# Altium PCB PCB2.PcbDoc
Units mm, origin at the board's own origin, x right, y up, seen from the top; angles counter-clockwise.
Board outline 184 x 101.95 mm, 2 copper layers (Top Layer, Bottom Layer); 27 components, 17 nets, 70 pads, 0 vias.
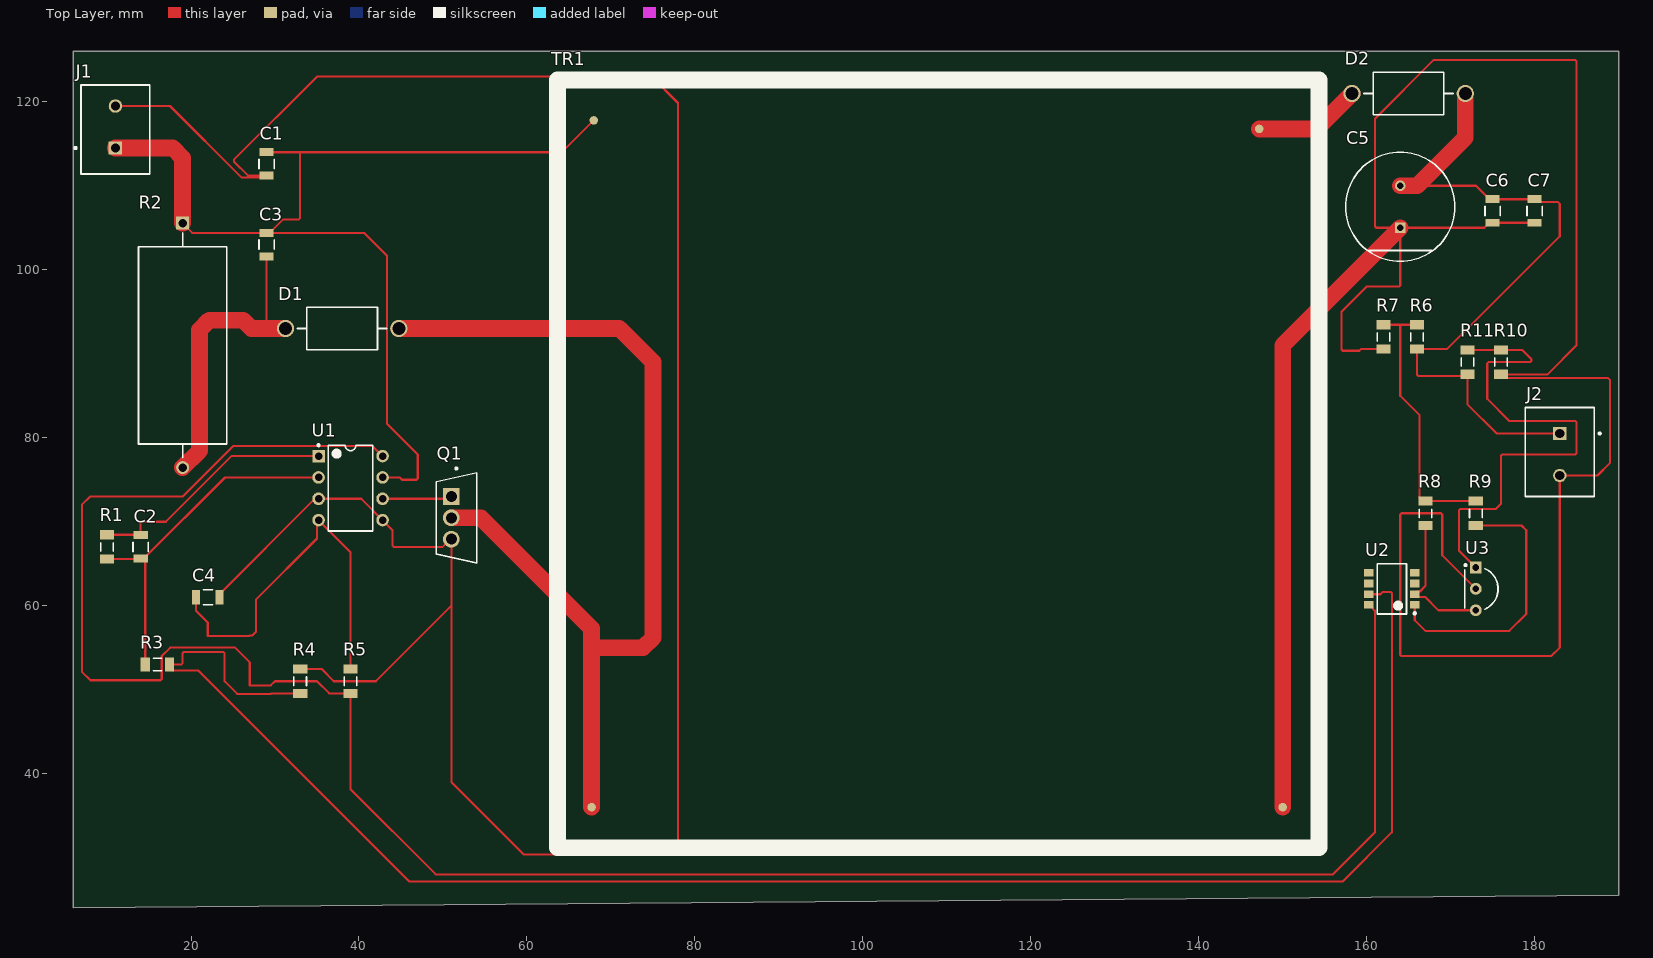
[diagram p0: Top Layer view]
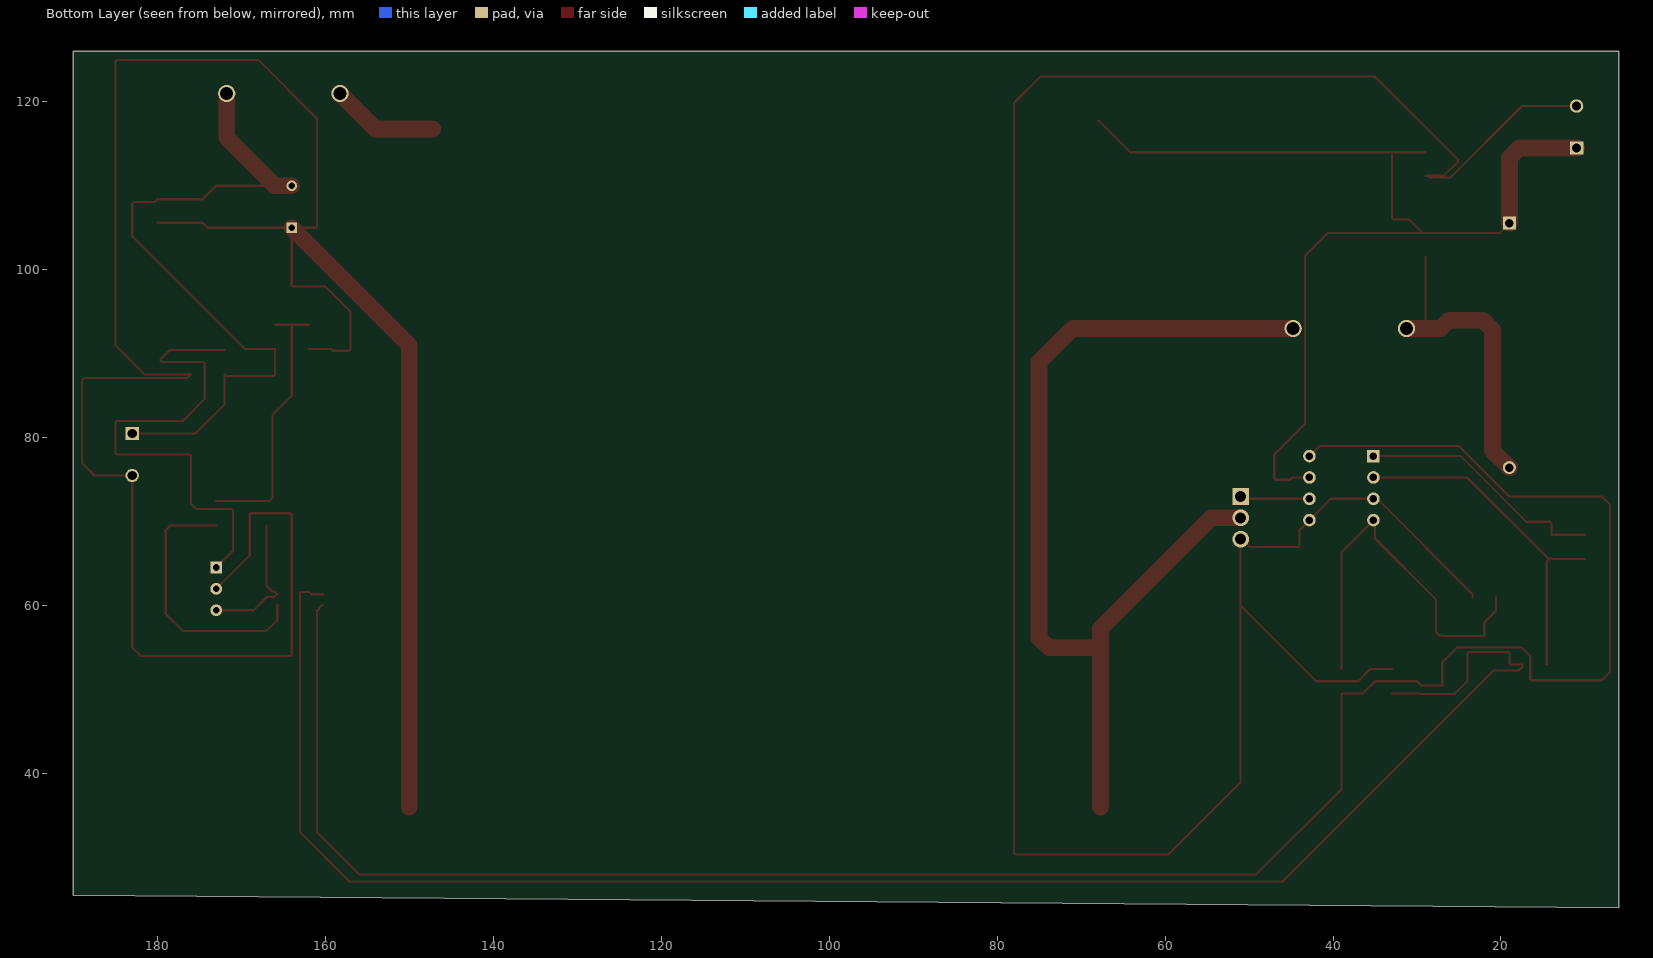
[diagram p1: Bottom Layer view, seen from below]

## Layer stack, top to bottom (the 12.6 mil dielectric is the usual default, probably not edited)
Top Solder: solder mask 0.0102, Solder Resist, Dk 3.5
Top Layer: signal copper 0.0356
Dielectric 1: dielectric 0.32, FR-4, Dk 4.8
Bottom Layer: signal copper 0.0356
Bottom Solder: solder mask 0.0102, Solder Resist, Dk 3.5

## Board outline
6,24.047 190,25.496 190,126 6,126
cut-out: 178.75,11.25

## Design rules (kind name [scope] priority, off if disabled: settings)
Clearance [All] p1: gap=0.254 ignorepadtopadclearanceinfootprint=FALSE except(0: Arc-Hole Track-Hole SMDPad-Hole THPad-Hole Via-Hole Fill-Hole Poly-Hole Region-Hole Text-Hole)
PolygonConnect [All] p1: connectstyle=Relief reliefconductorwidth=0.254 reliefentries=4 polygonreliefangle="90 Angle" airgapwidth=0.254
RoutingVias [All] p1: holewidth=0.711 width=1.27 viastyle="Through Hole" minholewidth=0.711 minwidth=1.27 maxholewidth=0.711 maxwidth=1.27
SolderMaskExpansion [All] p1: expansion=0.102 istentingtop=FALSE
Width [All] p1: maxlimit=22.254 minlimit=0.254 preferedwidth=0.254 minimp=50.000000 maximp=50.000000 favimp=50.000000
30 further rules are at their usual default settings.

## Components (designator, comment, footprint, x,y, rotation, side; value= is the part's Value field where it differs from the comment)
C1 "4.7uF (1206)" FP-C1206C-EB-MFG 29,112.6 r270 top value="1,000 pF"
C2 "1nF (1206)" FP-C1206C-EB-MFG 14,67 r90 top value="1,000 pF"
C3 "4.7uF (1206)" FP-C1206C-EB-MFG 29,103 r270 top value="1,000 pF"
C4 "1nF (1206)" FP-C1206C-EB-MFG 22,61 r0 top value="1,000 pF"
C5 "CAP 100uF UBX2A101MHL" FP-UBX2A101MHL-MFG 164,107.5 r90 top value=100uF
C6 "20uF (1206)" FP-C1206C-EB-MFG 175,107 r90 top value="1,000 pF"
C7 "1nF (1206)" FP-C1206C-EB-MFG 180,107 r90 top value="1,000 pF"
D1 "Schottky (MBR3100RLG)" ONSC-AXIAL_LEAD-2-267-05_V 38,93 r0 top
D2 "MUR460" ONSC-AXIAL_LEAD-2-267-05_V 165,121 r180 top
J1 "282836-2" TECO-282836-2_V 11,117 r90 top
J2 "282836-2" TECO-282836-2_V 183,78 r270 top
Q1 "IRFI540N (TO-220)" FP-PG-TO220-3-MFG 51.61,70.46 r0 top
R1 "10k Ohm (1206)" RESC3216X60X45NL10T20 10,67 r270 top
R2 "5W (300-1k Ohm)" FP-SQP500-MFG 19,91 r270 top value=1.2Ω
R3 "4.99k Ohm (1206)" RESC3216X60X45NL10T20 16,53 r180 top
R4 "7.68k Ohm (1206)" RESC3216X60X45NL10T20 33,51 r270 top
R5 "8.66k Ohm (1206)" RESC3216X60X45NL10T20 39,51 r90 top
R6 "6k Ohm (1206)" RESC3216X60X45NL10T20 166,92 r90 top
R7 "3k Ohm (1206)" RESC3216X60X45NL10T20 162,92 r270 top
R8 "13.7k Ohm (1206)" RESC3216X60X45NL10T20 167,71 r270 top
R9 "15.4k Ohm (1206)" RESC3216X60X45NL10T20 173,71 r270 top
R10 "3.01k Ohm (1206)" RESC3216X60X45NL10T20 176,89 r270 top
R11 "54.9k Ohm (1206)" RESC3216X60X45NL10T20 172,89 r90 top
TR1 "transformer" Transformer_flyback 67.958,35.746 r0 top
U1 "UC3845N" P0008A 39,74 r0 top
U2 "ILD217T (SOIC-8)" VISH-SOIC-8_C_V 163,62 r180 top
U3 "TL431ILP (TO92-3)" LP0003A 173,62 r0 top

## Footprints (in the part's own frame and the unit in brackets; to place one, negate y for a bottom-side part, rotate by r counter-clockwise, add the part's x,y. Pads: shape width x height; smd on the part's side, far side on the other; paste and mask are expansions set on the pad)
FP-C1206C-EB-MFG [mm]
  rect 0.95x1.7 smd paste+0 mask+0: 1(-1.4,0) 2(1.4,0)
  silkscreen extent -0.55,-0.9 0.55,0.9, body extent -2,-1 2,1, height 0.25
FP-PG-TO220-3-MFG [mm]
  rect 2x2 hole 1.3 paste-1000 mask+0: 1(-0.61,2.54)
  round 2 hole 1.3 paste-1000 mask+0: 2(-0.61,0) 3(-0.61,-2.54)
  silkscreen extent -2.41,-5.38 2.41,6, body extent -2.51,-5.6 2.51,5.6, height 0.25
FP-SQP500-MFG [mm]
  rect 1.55x1.55 hole 1 paste-1000 mask+0: 1(-14.555,0)
  round 1.55 hole 1 paste-1000 mask+0: 2(14.555,0)
  silkscreen extent -13.38,-5.25 13.38,5.25, body extent -15.43,-5.35 15.43,5.35, height 0.25
FP-UBX2A101MHL-MFG [mm]
  rect 1.25x1.25 hole 0.75 paste-1000 mask+0: 1(-2.5,0)
  round 1.25 hole 0.75 paste-1000 mask+0: 2(2.5,0)
  silkscreen extent -6.5,-6.5 6.5,6.5, body extent -6.6,-6.6 6.6,6.6, height 0.25
LP0003A [mm] "TO, Flat Index; 3 In-Line, Formed Axial Leads; Body Dia. 4.8mm; Leads 0.56 x 0.41 mm (max)"
  rrect7% 1.4x1.4 hole 0.8: 1(0,2.54)
  round 1.4 hole 0.8: 2(0,0) 3(0,-2.54)
  silkscreen extent -1.35,-2.41 2.65,2.95, body extent -1.33,-2.83 2.35,2.83, height 9.01
ONSC-AXIAL_LEAD-2-267-05_V [mm] "AXIAL, 2-Leads, Diameter 5.05mm"
  round 2.05 hole 1.55: 1(-6.745,0) 2(6.745,0)
  silkscreen extent -5.32,-2.52 5.32,2.52
P0008A [mm] "DIP, 8-Leads, Body 10.15x6.6mm, Pitch 2.54mm"
  rect 1.5x1.5 hole 0.9: 1(-3.81,3.81)
  round 1.5 hole 0.9: 2(-3.81,1.27) 3(-3.81,-1.27) 4(-3.81,-3.81) 5(3.81,-3.81) 6(3.81,-1.27) 7(3.81,1.27) 8(3.81,3.81)
  silkscreen extent -3.93,-5.1 2.65,5.23, body extent -3.95,-5.07 3.95,5.07, height 5.08
RESC3216X60X45NL10T20 [mm] "Chip Resistor, 2-Leads, Body 3.20x1.60mm, IPC Medium Density"
  rect 1.1x1.7 smd: 1(-1.45,0) 2(1.45,0)
  silkscreen extent -0.5,-0.75 0.5,0.75, body extent -1.65,-0.85 1.65,0.85, height 0.6
TECO-282836-2_V [mm] "Female Header, Pitch 5mm, 1 x 2 Position, Height 10mm"
  rect 1.6x1.6 hole 1.1: 1(-2.5,0)
  round 1.6 hole 1.1: 2(2.5,0)
  silkscreen extent -5.6,-4.1 5,4.87, body extent -5.6,-4.1 5,4.1, height 10
Transformer_flyback [mil]
  round 40 smd mask+100: 1(0,3230) 2(-10,10) 3(3120,3190) 4(3230,10)
  silkscreen extent -170,-180 3400,3420
VISH-SOIC-8_C_V [mm] "SOIC, 8-Leads, Body 6x4mm, Pitch 1.27mm"
  rect 1.14x0.91 smd: 1(-2.73,1.905) 2(-2.73,0.635) 3(-2.73,-0.635) 4(-2.73,-1.905) 5(2.73,-1.905) 6(2.73,-0.635) 7(2.73,0.635) 8(2.73,1.905)
  silkscreen extent -2.86,-3 1.75,3.03, body extent -3,-3 3,3, height 3.46

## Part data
C1 C2 C3 C4 C6 C7: library part CMP-03020-000955-1, "Multilayer Ceramic Capacitor, C Series, 1000 Pf, - 5%, C0g / Np0, 100 V, 1206 [3216 Metric] Rohs Compliant: Yes", Capacitance="1,000 pF", Manufacturer=KEMET, Manufacturer Part Number=C1206C102J1GACTU, Package=C1206C-EB, Temperature="-55°C to +150°C", Temperature Characteristic=C0G, Temperature Coefficient=15%, Temperature Range High=+150°C, Temperature Range Low=-55°C, Tolerance=0.05, Voltage Rating="100 V"
C5: library part CMP-12462-000004-1, "CAP ALUM 100UF 20% 100V RADIAL", Capacitance=100uF, Leakage Current=300uA, Manufacturer=Nichicon, Manufacturer Part Number=UBX2A101MHL, Package=0, Ripple Current=950mA, Temperature="-55°C to +150°C", Temperature Range High=+150°C, Temperature Range Low=-55°C, Tolerance=20%, Voltage Rating=100V
D1: library part CMP-1055-00020-1, "Rectifier, 2-Pin Axial_Lead, Pb-Free, Tape and Reel", Manufacturer="On Semiconductor", PartNumber=MBR3100RLG
D2: library part CMP-0902-00067-1, "SWITCHMODE(TM) Power Rectifier, 2-Pin Axial_Lead, Pb-Free, Bulk Bag", Manufacturer="On Semiconductor"
J1 J2: library part CMP-1684-00017-1, "Female Header, Pitch 5 mm, 1 x 2 Position, Height 10 mm, Tail Length 3.5 mm, Rohs, Bulk", Color=Green, Current=13.5A, Manufacturer="TE Connectivity", Package Description="Female Header, Pitch 5 mm, 1 x 2 Position, Height 10 mm, Tail Length 3.5 mm", Package Reference=THD, Standard Package=300, Voltage=300V
Q1: library part CMP-32901-000575-1, "MOSFET N-CH 100V 20A TO220FP", Case/Package=TO-220-3, Continuous Drain Current (ID)=20A, Drain to Source Breakdown Voltage=100V, Drain to Source Resistance=52mR, Gate to Source Voltage (Vgs)=20V, Max Operating Temperature=175°C, Max Power Dissipation=54W, Min Operating Temperature=-55°C, Threshold Voltage=4V, Input Capacitance=1.4nF
R1 R3 R4 R5 R6 R7 R8 R9 R10 R11: library part CMP-2003-02424-1, Manufacturer="Vishay Dale", Part Number=CRCW12068R25FKEA
R2: library part CMP-03413-000003-1, Manufacturer=Yageo, Manufacturer Part Number=SQP500JB-1R2, Package=SQP500, Power Rating=5W, Resistance=1.2Ω, Temperature="-55°C to +155°C", Temperature Coefficient=300ppm/°C, Temperature Range High=+155°C, Temperature Range Low=-55°C, Tolerance=5%, Voltage Rating=350V
U1: library part CMP-0319-00305-2, "PWM Controller with Current Control, 50 % Duty Cycle, 0 to +70 degC, 8-pin PDIP (P), Green (RoHS & no Sb/Br)", Frequency(Max)(kHz)=450, Manufacturer="Texas Instruments", Rating=Catalog
U2: library part CMP-2000-06453-1, "Optocoupler, Phototransistor Output, Dual Channel, 4000 VRMS, -55 to 100 degC, 8-Pin SOIC, RoHS, Tape and Reel", Current - DC Forward (If) (Max)=30mA, Current - Output / Channel=-, Current Transfer Ratio (Max)=200%@10mA, Current Transfer Ratio (Min)=100%@10mA, Manufacturer=Vishay, Operating Temperature=-55°C~100°C, Package / Case="8-SOIC(0.154\",3.90mmWidth)", Package Description="8-Pin Small Outline Integrated Circuit, Body 5.84 x 3.91 mm, Pitch 1.27 mm", Package Reference=SOIC-8, Standard Package=1, Supplier Device Package=8-SOIC, Voltage - Forward (Vf) (Typ)=1.2V, Voltage - Output (Max)=70V, Voltage - Isolation=4000Vrms
U3: library part CMP-0366-00043-2, "Adjustable Precision Shunt Regulator, 34 ppm / degC, 100 mA, -40 to 85 degC, 3-pin TO-92 (LP), Pb-Free (RoHS)", Manufacturer="Texas Instruments", PartNumber=TL431ILP, Rating=Military, Temp Coeff(Max)(ppm/ degree C)=92, Temp Coeff(Typ)(ppm/ degree C)=34

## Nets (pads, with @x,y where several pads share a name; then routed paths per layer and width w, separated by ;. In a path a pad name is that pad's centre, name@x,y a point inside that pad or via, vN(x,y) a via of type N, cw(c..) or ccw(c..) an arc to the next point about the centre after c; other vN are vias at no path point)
GND: C1.2 C4.2 J1.2 Q1.3 R4.1 U1.3 U1.5 | length 292.2
  Top Layer w0.254: J1.2 17.5,119.5 26,111 28.5,111 C1.2@28.7,111.2 ; C4.2 23.4,61.375 34.517,72.492 34.952,72.492 U1.3 40.27,72.73 U1.5 44,69 44,67.149 44.149,67 49.967,67 50.887,67.92 Q1.3 51,60 ; C1.2 C1.2@28.7,111.2 ; R4.1 35.55,52.45 37,51 42,51 51,60 ; C1.2@28.7,111.2 26.8,111.2 25.105,112.895 25.105,113.105 35,123 74.851,123 78,119.851 78,30.508 77.851,30.359 59.641,30.359 51,39 51,60
NetC1_1: C1.1 C3.1 J1.1 R2.1 TR1.1 U1.7 | length 127.3
  Top Layer w0.254: R2.1 20.155,104.4 C3.1 C3.1@29.375,104.4 ; C1.1 33,114 ; U1.7 44.864,75.27 45.134,75 46.851,75 47,75.149 47,78 43.339,81.661 43.339,101.661 40.6,104.4 C3.1@29.375,104.4 ; TR1.1 64.17,114 33,114 ; C3.1@29.375,104.4 30.975,106 32.851,106 33,106.149 33,114
  Top Layer w2: J1.1 17.828,114.5 19,113.328 R2.1
NetC2_1: C2.1 R1.2 R3.2 U1.2 | length 41.9
  Top Layer w0.254: R1.2 C2.1@14,65.55 ; C2.1 14.202,65.6 C2.1@14.252,65.55 ; R3.2 14.55,65.252 C2.1@14.252,65.55 ; U1.2 24.045,75.27 14.325,65.55 C2.1@14.252,65.55
NetC2_2: C2.2 R1.1 U1.1 | length 30
  Top Layer w0.254: R1.1 13.95,68.45 C2.2 14,69.851 14.149,70 17,70 24.81,77.81 U1.1
NetC3_2: C3.2 D1.1 R2.2 | length 37
  Top Layer w0.254: 29,93 C3.2
  Top Layer w2: R2.2 21,78.445 21,92.828 22.172,94 26.207,94 27.207,93 29,93 D1.1
NetC4_1: C4.1 R5.2 U1.4 | length 46.8
  Top Layer w0.254: C4.1 20.6,59.4 22,58 22,56.4 26.95,56.4 27,56.45 27.3,56.45 27.723,56.873 27.723,60.723 35,68 35,70 U1.4 39,66.38 R5.2
NetC5_2: C5.2 C6.2 C7.2 D2.1 J2.1 R6.1 R11.1 | length 84.9
  Top Layer w0.254: 166,110 173.025,110 174.625,108.4 C6.2 C7.2 180.348,108.052 182.799,108.052 183,107.851 183,104 169.55,90.55 R6.1 166,87.508 166.149,87.359 171.809,87.359 R11.1 172,84 175.5,80.5 J2.1
  Top Layer w2: C5.2 166,110 171.745,115.745 D2.1
NetD1_2: D1.2 Q1.2 TR1.2 | length 116
  Top Layer w2: D1.2 71,93 75,89 75,56.172 73.828,55 67.704,55 ; Q1.2 54.54,70.46 67.704,57.296 67.704,55 ; TR1.2 67.704,55
NetD2_2: D2.2 TR1.3 | length 12.8
  Top Layer w2: TR1.3 154.027,116.772 D2.2
NetQ1_1: Q1.1 U1.6 | length 8.6
  Top Layer w0.254: U1.6@43.002,72.922 U1.6 50.73,72.73 Q1.1
NetR3_1: R3.1 R4.2 U2.7 | length 211.2
  Top Layer w0.254: R4.2 29.562,49.55 29.504,49.492 25.508,49.492 24,51 24,54.343 23.851,54.492 19.149,54.492 19,54.343 19,53.149 18.851,53 R3.1 17.45,52.7 17.873,52.277 20.872,52.277 46,27.149 157.149,27.149 163,33 163,61.492 162.851,61.641 161.92,61.641 161.644,61.365 U2.7
NetR5_1: R5.1 U1.8 U2.8 | length 266.1
  Top Layer w0.254: U1.8 41.62,79 25,79 19,73 8,73 7,72 7,52.149 8.029,51.12 16.37,51.12 16.519,51.269 16.519,54.008 17.511,55 25.25,55 27,53.25 27,50.508 29.508,50.508 30,51 35,51 36.45,49.55 R5.1 39,38.149 49.149,28 156,28 161,33 161,59.365 160.713,59.652 160.713,59.767 160.385,60.095 U2.8
NetR6_2: R6.2 R7.1 R8.1 R9.1 | length 32.4
  Top Layer w0.254: R7.1 164,93.45 ; R6.2 164,93.45 ; R9.1 R8.1 166.7,72.45 166.277,72.873 166.277,82.723 164,85 164,93.45
NetR8_2: R8.2 U2.2 U3.3 | length 16.9
  Top Layer w0.254: R8.2 167,62.341 166.352,61.693 166.058,61.693 U2.2 165.845,61.365 166.173,61.037 166.963,61.037 168.54,59.46 U3.3
NetR9_2: R9.2 U2.1 | length 32.7
  Top Layer w0.254: U2.1 165.73,58.27 167,57 177,57 179,59 179,69 178.45,69.55 R9.2
NetR10_1: R10.1 R11.2 U3.1 | length 61.2
  Top Layer w0.254: R11.2 178.55,90.45 179.641,89.359 179.641,89.149 179.492,89 174.508,89 174.359,88.851 174.359,84.641 177,82 184.851,82 185,81.851 185,78.149 184.851,78 176.149,78 176,77.851 176,72.149 175.37,71.519 171.149,71.519 171,71.37 171,66.54 U3.1
SGND: C5.1 C6.1 C7.1 J2.2 R7.2 R10.2 TR1.4 U3.2 | length 305.1
  Top Layer w0.254: R7.2 159.308,90.55 159.117,90.359 157.149,90.359 157,90.508 157,95 160,98 163.851,98 164,98.149 C5.1 ; U3.2 169,66 169,70.851 168.851,71 164.149,71 164,70.851 164,54.149 164.149,54 182,54 183,55 J2.2 187.5,75.5 189,77 189,86.851 188.724,87.127 176.423,87.127 R10.2 181.55,87.55 185,91 185,124.851 184.851,125 168,125 161,118 161,105.149 161.149,105 C5.1 ; C7.1 C6.1 174.625,105.6 174.025,105 C5.1
  Top Layer w2: TR1.4 150,91 C5.1
pads on no net: U2.3 U2.4 U2.5 U2.6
